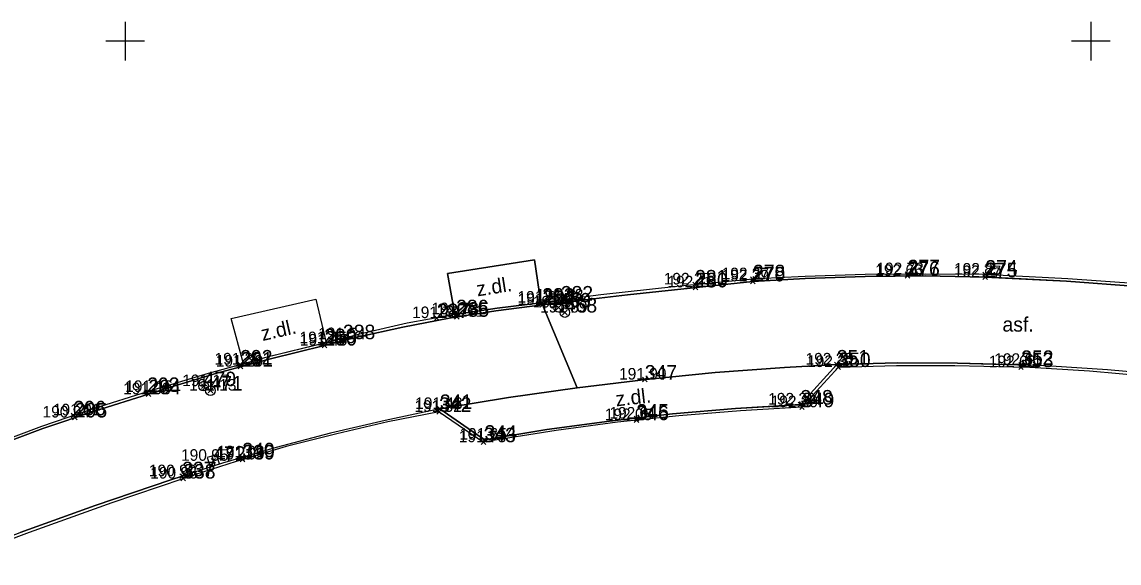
# Model space of a CAD drawing. Extents: x -706861 to -706379, y -1036456 to -1036201.
# Drawn here: x -706805.3 to -706748.5, y -1036327 to -1036299 of the extents above; entities that cross this region are included whole.
import ezdxf

# ---------------------------------------------------------------- set-up
doc = ezdxf.new("R2010")
doc.units = 0
for name, color, linetype in [('18_popisy', 7, 'Continuous'), ('29_vodovod', 7, 'Continuous'), ('30_kanalizace splašková', 7, 'Continuous'), ('40_plochy', 7, 'Continuous'), ('51_body polohopisu_značky', 7, 'Continuous'), ('52_body polohopisu_čísla', 7, 'Continuous'), ('53_body polohopisu_výšky', 7, 'Continuous'), ('54_body polohopisu_čísla nadbytečné pro kreslení', 7, 'Continuous'), ('5_rozhraní ploch', 7, 'Continuous'), ('60_mapový rám_legenda', 7, 'Continuous')]:
    doc.layers.add(name, color=color, linetype=linetype)

msp = doc.modelspace()

# ---------------------------------------------------------------- linework, layer by layer
at = {"layer": '29_vodovod'}
for centre in [(-706777.55, -1036313.77), (-706795.93, -1036317.84)]:
    msp.add_circle(centre, 0.25, dxfattribs=at)
at = {"layer": '30_kanalizace splašková'}
msp.add_line((-706795.503, -1036321.461), (-706795.357, -1036321.939), dxfattribs=at)
msp.add_lwpolyline([(-706795.743, -1036321.534), (-706795.597, -1036322.013), (-706795.117, -1036321.866), (-706795.264, -1036321.388)], close=True, dxfattribs=at)
for centre in [(-706777.23, -1036314.03), (-706795.58, -1036318.07)]:
    msp.add_circle(centre, 0.25, dxfattribs=at)
at = {"layer": '40_plochy'}
for points in [[(-706778.481, -1036313.53), (-706778.809, -1036311.306), (-706783.303, -1036312.02), (-706782.918, -1036314.135), (-706780.74, -1036313.8)], [(-706793.873, -1036316.683), (-706794.511, -1036314.335), (-706790.123, -1036313.337), (-706789.59, -1036315.594), (-706792.71, -1036316.36)], [(-706783.7, -1036319.02), (-706780.15, -1036318.43), (-706776.59, -1036317.92), (-706773.02, -1036317.49), (-706769.44, -1036317.14), (-706765.85, -1036316.87), (-706763.15, -1036316.72), (-706765.03, -1036318.79), (-706768.4, -1036319), (-706771.66, -1036319.28), (-706774.92, -1036319.65), (-706778.16, -1036320.09), (-706781.39, -1036320.61)]]:
    msp.add_lwpolyline(points, close=True, dxfattribs=at)
for points in [[(-706746.24, -1036317.25), (-706749.14, -1036316.99), (-706752.05, -1036316.81), (-706753.6, -1036316.74), (-706756.9, -1036316.65), (-706760.02, -1036316.64), (-706763.15, -1036316.72), (-706765.85, -1036316.87), (-706769.44, -1036317.14), (-706773.02, -1036317.49), (-706776.59, -1036317.92), (-706778.39, -1036313.64), (-706773.99, -1036313.12), (-706767.49, -1036312.42), (-706764.78, -1036312.27), (-706761.68, -1036312.16), (-706758.57, -1036312.14), (-706755.47, -1036312.2), (-706751.26, -1036312.41), (-706747.58, -1036312.68)], [(-706806.94, -1036321.03), (-706804.25, -1036320.03), (-706801.53, -1036319.11), (-706798.79, -1036318.26), (-706798, -1036318), (-706795.24, -1036317.17), (-706792.47, -1036316.42), (-706789.67, -1036315.74), (-706787.99, -1036315.31), (-706785.61, -1036314.78), (-706783.22, -1036314.32), (-706780.81, -1036313.94), (-706778.39, -1036313.64), (-706776.59, -1036317.92), (-706780.15, -1036318.43), (-706783.7, -1036319.02), (-706786.54, -1036319.61), (-706789.36, -1036320.27), (-706792.17, -1036321.01), (-706794.95, -1036321.83), (-706797.04, -1036322.5), (-706797.63, -1036322.69), (-706801.54, -1036324.01), (-706805.43, -1036325.41)]]:
    msp.add_lwpolyline(points, dxfattribs=at)
at = {"layer": '51_body polohopisu_značky'}
for points in [[(-706767.61, -1036312.43), (-706767.37, -1036312.19)], [(-706767.61, -1036312.19), (-706767.37, -1036312.43)], [(-706767.61, -1036312.54), (-706767.37, -1036312.3)], [(-706767.61, -1036312.3), (-706767.37, -1036312.54)], [(-706759.61, -1036312.26), (-706759.37, -1036312.02)], [(-706759.61, -1036312.02), (-706759.37, -1036312.26)], [(-706759.6, -1036312.17), (-706759.36, -1036311.93)], [(-706759.6, -1036311.93), (-706759.36, -1036312.17)], [(-706755.59, -1036312.32), (-706755.35, -1036312.08)], [(-706755.59, -1036312.08), (-706755.35, -1036312.32)], [(-706755.58, -1036312.19), (-706755.34, -1036311.95)], [(-706755.58, -1036311.95), (-706755.34, -1036312.19)], [(-706770.61, -1036312.7), (-706770.37, -1036312.46)], [(-706770.61, -1036312.46), (-706770.37, -1036312.7)], [(-706770.59, -1036312.85), (-706770.35, -1036312.61)], [(-706770.59, -1036312.61), (-706770.35, -1036312.85)], [(-706778.52, -1036313.64), (-706778.28, -1036313.4)], [(-706778.52, -1036313.4), (-706778.28, -1036313.64)], [(-706778.51, -1036313.76), (-706778.27, -1036313.52)], [(-706778.51, -1036313.52), (-706778.27, -1036313.76)], [(-706777.56, -1036313.53), (-706777.32, -1036313.29)], [(-706777.56, -1036313.29), (-706777.32, -1036313.53)], [(-706782.98, -1036314.24), (-706782.74, -1036314)], [(-706782.98, -1036314), (-706782.74, -1036314.24)], [(-706777.67, -1036313.89), (-706777.43, -1036313.65)], [(-706777.67, -1036313.65), (-706777.43, -1036313.89)], [(-706777.35, -1036314.15), (-706777.11, -1036313.91)], [(-706777.35, -1036313.91), (-706777.11, -1036314.15)], [(-706783.98, -1036314.44), (-706783.74, -1036314.2)], [(-706783.98, -1036314.2), (-706783.74, -1036314.44)], [(-706782.94, -1036314.37), (-706782.7, -1036314.13)], [(-706782.94, -1036314.13), (-706782.7, -1036314.37)], [(-706789.81, -1036315.74), (-706789.57, -1036315.5)], [(-706789.81, -1036315.5), (-706789.57, -1036315.74)], [(-706789.79, -1036315.86), (-706789.55, -1036315.62)], [(-706789.79, -1036315.62), (-706789.55, -1036315.86)], [(-706788.84, -1036315.53), (-706788.6, -1036315.29)], [(-706788.84, -1036315.29), (-706788.6, -1036315.53)], [(-706794.16, -1036316.84), (-706793.92, -1036316.6)], [(-706794.16, -1036316.6), (-706793.92, -1036316.84)], [(-706794.14, -1036316.95), (-706793.9, -1036316.71)], [(-706794.14, -1036316.71), (-706793.9, -1036316.95)], [(-706763.27, -1036316.84), (-706763.03, -1036316.6)], [(-706763.27, -1036316.6), (-706763.03, -1036316.84)], [(-706763.19, -1036316.97), (-706762.95, -1036316.73)], [(-706763.19, -1036316.73), (-706762.95, -1036316.97)], [(-706753.73, -1036316.98), (-706753.49, -1036316.74)], [(-706753.73, -1036316.74), (-706753.49, -1036316.98)], [(-706753.72, -1036316.86), (-706753.48, -1036316.62)], [(-706753.72, -1036316.62), (-706753.48, -1036316.86)], [(-706773.21, -1036317.62), (-706772.97, -1036317.38)], [(-706773.21, -1036317.38), (-706772.97, -1036317.62)], [(-706798.97, -1036318.26), (-706798.73, -1036318.02)], [(-706798.97, -1036318.02), (-706798.73, -1036318.26)], [(-706796.05, -1036317.96), (-706795.81, -1036317.72)], [(-706796.05, -1036317.72), (-706795.81, -1036317.96)], [(-706795.7, -1036318.19), (-706795.46, -1036317.95)], [(-706795.7, -1036317.95), (-706795.46, -1036318.19)], [(-706798.91, -1036318.38), (-706798.67, -1036318.14)], [(-706798.91, -1036318.14), (-706798.67, -1036318.38)], [(-706783.86, -1036319.29), (-706783.62, -1036319.05)], [(-706783.86, -1036319.05), (-706783.62, -1036319.29)], [(-706783.82, -1036319.14), (-706783.58, -1036318.9)], [(-706783.82, -1036318.9), (-706783.58, -1036319.14)], [(-706765.15, -1036318.91), (-706764.91, -1036318.67)], [(-706765.15, -1036318.67), (-706764.91, -1036318.91)], [(-706765.07, -1036319.05), (-706764.83, -1036318.81)], [(-706765.07, -1036318.81), (-706764.83, -1036319.05)], [(-706802.79, -1036319.47), (-706802.55, -1036319.23)], [(-706802.79, -1036319.23), (-706802.55, -1036319.47)], [(-706802.72, -1036319.58), (-706802.48, -1036319.34)], [(-706802.72, -1036319.34), (-706802.48, -1036319.58)], [(-706773.64, -1036319.64), (-706773.4, -1036319.4)], [(-706773.64, -1036319.4), (-706773.4, -1036319.64)], [(-706773.64, -1036319.72), (-706773.4, -1036319.48)], [(-706773.64, -1036319.48), (-706773.4, -1036319.72)], [(-706781.56, -1036320.86), (-706781.32, -1036320.62)], [(-706781.56, -1036320.62), (-706781.32, -1036320.86)], [(-706781.51, -1036320.73), (-706781.27, -1036320.49)], [(-706781.51, -1036320.49), (-706781.27, -1036320.73)], [(-706794.05, -1036321.64), (-706793.81, -1036321.4)], [(-706794.05, -1036321.4), (-706793.81, -1036321.64)], [(-706795.55, -1036321.82), (-706795.31, -1036321.58)], [(-706795.55, -1036321.58), (-706795.31, -1036321.82)], [(-706794.04, -1036321.75), (-706793.8, -1036321.51)], [(-706794.04, -1036321.51), (-706793.8, -1036321.75)], [(-706797.16, -1036322.62), (-706796.92, -1036322.38)], [(-706797.16, -1036322.38), (-706796.92, -1036322.62)], [(-706797.11, -1036322.74), (-706796.87, -1036322.5)], [(-706797.11, -1036322.5), (-706796.87, -1036322.74)]]:
    msp.add_lwpolyline(points, dxfattribs=at)
at = {"layer": '5_rozhraní ploch'}
for points in [[(-706782.918, -1036314.135), (-706783.303, -1036312.02), (-706778.809, -1036311.306), (-706778.481, -1036313.53)], [(-706767.49, -1036312.31), (-706771.43, -1036312.68), (-706775.36, -1036313.12), (-706778.4, -1036313.52)], [(-706755.46, -1036312.07), (-706758.57, -1036312.04), (-706761.68, -1036312.06), (-706764.78, -1036312.17), (-706766.22, -1036312.24), (-706767.49, -1036312.31)], [(-706758.57, -1036312.14), (-706761.68, -1036312.16), (-706764.78, -1036312.27), (-706767.49, -1036312.42)], [(-706736.58, -1036313.96), (-706740.24, -1036313.45), (-706743.9, -1036313.03), (-706747.58, -1036312.68), (-706751.26, -1036312.41), (-706754.94, -1036312.22), (-706755.47, -1036312.2), (-706758.57, -1036312.14)], [(-706736.58, -1036313.83), (-706740.22, -1036313.32), (-706743.87, -1036312.9), (-706747.52, -1036312.55), (-706751.19, -1036312.28), (-706754.86, -1036312.09), (-706755.46, -1036312.07)], [(-706767.49, -1036312.42), (-706773.99, -1036313.12), (-706778.39, -1036313.64)], [(-706793.873, -1036316.683), (-706794.511, -1036314.335), (-706790.123, -1036313.337), (-706789.59, -1036315.594)], [(-706778.4, -1036313.52), (-706778.481, -1036313.53), (-706780.74, -1036313.8), (-706782.918, -1036314.135), (-706783.08, -1036314.16), (-706785.4, -1036314.59), (-706787.7, -1036315.11), (-706789.59, -1036315.594), (-706789.69, -1036315.62)], [(-706778.39, -1036313.64), (-706780.81, -1036313.94), (-706783.22, -1036314.32), (-706785.61, -1036314.78), (-706787.99, -1036315.31), (-706789.67, -1036315.74)], [(-706789.69, -1036315.62), (-706792.71, -1036316.36), (-706793.873, -1036316.683), (-706795.7, -1036317.19), (-706798.68, -1036318.08), (-706798.85, -1036318.14)], [(-706789.67, -1036315.74), (-706792.47, -1036316.42), (-706795.24, -1036317.17), (-706798, -1036318), (-706798.79, -1036318.26)], [(-706783.7, -1036319.02), (-706780.15, -1036318.43), (-706776.59, -1036317.92), (-706773.02, -1036317.49), (-706769.44, -1036317.14), (-706765.85, -1036316.87), (-706763.15, -1036316.72)], [(-706765.03, -1036318.79), (-706763.15, -1036316.72)], [(-706764.95, -1036318.93), (-706763.06, -1036316.85)], [(-706763.15, -1036316.72), (-706760.02, -1036316.64), (-706756.9, -1036316.65), (-706753.77, -1036316.73), (-706753.6, -1036316.74)], [(-706763.06, -1036316.85), (-706760.05, -1036316.77), (-706757.04, -1036316.77), (-706754.03, -1036316.84), (-706753.61, -1036316.86)], [(-706734.78, -1036319.22), (-706737.81, -1036318.63), (-706740.86, -1036318.12), (-706743.92, -1036317.69), (-706746.99, -1036317.34), (-706750.07, -1036317.07), (-706753.15, -1036316.88), (-706753.61, -1036316.86)], [(-706734.76, -1036319.1), (-706737.61, -1036318.52), (-706740.48, -1036318.02), (-706743.36, -1036317.6), (-706746.24, -1036317.25), (-706749.14, -1036316.99), (-706752.05, -1036316.81), (-706753.6, -1036316.74)], [(-706798.85, -1036318.14), (-706801.6, -1036318.99), (-706804.32, -1036319.92), (-706807.01, -1036320.93), (-706809.68, -1036322.01), (-706810.11, -1036322.19)], [(-706798.79, -1036318.26), (-706801.53, -1036319.11), (-706804.25, -1036320.03), (-706806.94, -1036321.03), (-706809.6, -1036322.1), (-706810.07, -1036322.3)], [(-706783.7, -1036319.02), (-706786.54, -1036319.61), (-706789.36, -1036320.27), (-706792.17, -1036321.01), (-706794.95, -1036321.83), (-706797.04, -1036322.5)], [(-706783.74, -1036319.17), (-706786.4, -1036319.69), (-706789.03, -1036320.3), (-706791.65, -1036320.97), (-706794.25, -1036321.73), (-706796.83, -1036322.56), (-706796.99, -1036322.62)], [(-706783.74, -1036319.17), (-706781.44, -1036320.74)], [(-706783.7, -1036319.02), (-706781.39, -1036320.61)], [(-706764.95, -1036318.93), (-706768.14, -1036319.11), (-706771.33, -1036319.37), (-706774.51, -1036319.71), (-706777.68, -1036320.14), (-706780.84, -1036320.64), (-706781.44, -1036320.74)], [(-706781.39, -1036320.61), (-706778.16, -1036320.09), (-706774.92, -1036319.65), (-706771.66, -1036319.28), (-706768.4, -1036319), (-706765.14, -1036318.8), (-706765.03, -1036318.79)], [(-706809.29, -1036326.88), (-706805.43, -1036325.41), (-706801.54, -1036324.01), (-706797.63, -1036322.69), (-706797.04, -1036322.5)], [(-706809.22, -1036326.99), (-706804.95, -1036325.39), (-706800.66, -1036323.86), (-706796.99, -1036322.62)]]:
    msp.add_lwpolyline(points, dxfattribs=at)
at = {"layer": '60_mapový rám_legenda'}
for points in [[(-706800, -1036299), (-706800, -1036300), (-706800, -1036301)], [(-706750, -1036299), (-706750, -1036300), (-706750, -1036301)], [(-706799, -1036300), (-706800, -1036300), (-706801, -1036300)], [(-706749, -1036300), (-706750, -1036300), (-706751, -1036300)]]:
    msp.add_lwpolyline(points, dxfattribs=at)

# ---------------------------------------------------------------- texts
at = {"layer": '18_popisy'}
for rotation, p in [(9.0278, (-706781.75, -1036313.2)), (12.8209, (-706792.874, -1036315.507)), (6.4752, (-706774.563, -1036318.888))]:
    msp.add_text('z.dl.', height=0.75, rotation=rotation, dxfattribs=at).set_placement(p)
msp.add_text('asf.', height=0.75, dxfattribs=at).set_placement((-706754.57, -1036315.02))
at = {"layer": '52_body polohopisu_čísla'}
for s, p in [('279', (-706767.49, -1036312.42)), ('277', (-706759.48, -1036312.05)), ('274', (-706755.46, -1036312.07)), ('280', (-706770.47, -1036312.73)), ('284', (-706778.39, -1036313.64)), ('287', (-706783.86, -1036314.32)), ('289', (-706789.69, -1036315.62)), ('292', (-706794.04, -1036316.72)), ('350', (-706763.07, -1036316.85)), ('353', (-706753.61, -1036316.86)), ('347', (-706773.09, -1036317.5)), ('293', (-706798.85, -1036318.14)), ('471', (-706795.58, -1036318.07)), ('296', (-706802.67, -1036319.35)), ('341', (-706783.7, -1036319.02)), ('349', (-706764.95, -1036318.93)), ('344', (-706781.39, -1036320.61)), ('339', (-706793.92, -1036321.63)), ('338', (-706796.99, -1036322.62))]:
    msp.add_text(s, height=0.75, dxfattribs=at).set_placement(p)
at = {"layer": '53_body polohopisu_výšky'}
for s, p in [('192 29 ', (-706769.113, -1036312.42)), ('192 37 ', (-706769.108, -1036312.31)), ('192 66 ', (-706761.158, -1036312.14)), ('192 73 ', (-706761.098, -1036312.05)), ('192 77 ', (-706757.088, -1036312.2)), ('192 85 ', (-706757.078, -1036312.07)), ('192 25 ', (-706772.108, -1036312.58)), ('192 18 ', (-706771.918, -1036312.73)), ('191 89 ', (-706779.683, -1036313.52)), ('191 98 ', (-706778.72, -1036313.41)), ('191 73 ', (-706784.138, -1036314.12)), ('191 89 ', (-706779.673, -1036313.64)), ('191 90 ', (-706778.882, -1036313.77)), ('191 89 ', (-706778.513, -1036314.03)), ('191 73 ', (-706785.138, -1036314.32)), ('191 71 ', (-706783.857, -1036314.25)), ('191 45 ', (-706790.968, -1036315.62)), ('191 45 ', (-706790.948, -1036315.74)), ('191 54 ', (-706789.998, -1036315.41)), ('191 30 ', (-706795.37, -1036316.72)), ('191 29 ', (-706795.303, -1036316.83)), ('192 28 ', (-706764.768, -1036316.72)), ('192 32 ', (-706764.688, -1036316.85)), ('192 66 ', (-706755.278, -1036316.86)), ('192 61 ', (-706754.994, -1036316.74)), ('191 90 ', (-706774.422, -1036317.5)), ('191 17 ', (-706797.038, -1036317.84)), ('191 13 ', (-706796.688, -1036318.07)), ('191 08 ', (-706800.094, -1036318.26)), ('191 16 ', (-706799.991, -1036318.14)), ('191 52 ', (-706785.018, -1036319.17)), ('191 48 ', (-706784.978, -1036319.02)), ('192 30 ', (-706766.7, -1036318.79)), ('192 39 ', (-706766.573, -1036318.93)), ('190 94 ', (-706804.272, -1036319.46)), ('191 01 ', (-706803.733, -1036319.35)), ('192 05 ', (-706775.164, -1036319.6)), ('192 01 ', (-706774.923, -1036319.52)), ('191 73 ', (-706782.718, -1036320.74)), ('191 65 ', (-706782.684, -1036320.61)), ('191 03 ', (-706795.234, -1036321.52)), ('190 95 ', (-706797.102, -1036321.7)), ('191 09 ', (-706795.229, -1036321.63)), ('190 90 ', (-706798.764, -1036322.5)), ('190 96 ', (-706798.695, -1036322.62))]:
    msp.add_text(s, height=0.6, dxfattribs=at).set_placement(p)
at = {"layer": '54_body polohopisu_čísla nadbytečné pro kreslení'}
for s, p in [('281', (-706770.49, -1036312.58)), ('278', (-706767.49, -1036312.31)), ('276', (-706759.49, -1036312.14)), ('275', (-706755.47, -1036312.2)), ('283', (-706778.4, -1036313.52)), ('282', (-706777.44, -1036313.41)), ('286', (-706782.86, -1036314.12)), ('285', (-706782.82, -1036314.25)), ('469', (-706777.55, -1036313.77)), ('468', (-706777.23, -1036314.03)), ('288', (-706788.72, -1036315.41)), ('290', (-706789.67, -1036315.74)), ('291', (-706794.02, -1036316.83)), ('351', (-706763.15, -1036316.72)), ('352', (-706753.6, -1036316.74)), ('294', (-706798.79, -1036318.26)), ('470', (-706795.93, -1036317.84)), ('348', (-706765.03, -1036318.79)), ('342', (-706783.74, -1036319.17)), ('295', (-706802.6, -1036319.46)), ('345', (-706773.52, -1036319.52)), ('346', (-706773.52, -1036319.6)), ('343', (-706781.44, -1036320.74)), ('340', (-706793.93, -1036321.52)), ('472', (-706795.43, -1036321.7)), ('337', (-706797.04, -1036322.5))]:
    msp.add_text(s, height=0.75, dxfattribs=at).set_placement(p)

doc.saveas('drawing.dxf')
